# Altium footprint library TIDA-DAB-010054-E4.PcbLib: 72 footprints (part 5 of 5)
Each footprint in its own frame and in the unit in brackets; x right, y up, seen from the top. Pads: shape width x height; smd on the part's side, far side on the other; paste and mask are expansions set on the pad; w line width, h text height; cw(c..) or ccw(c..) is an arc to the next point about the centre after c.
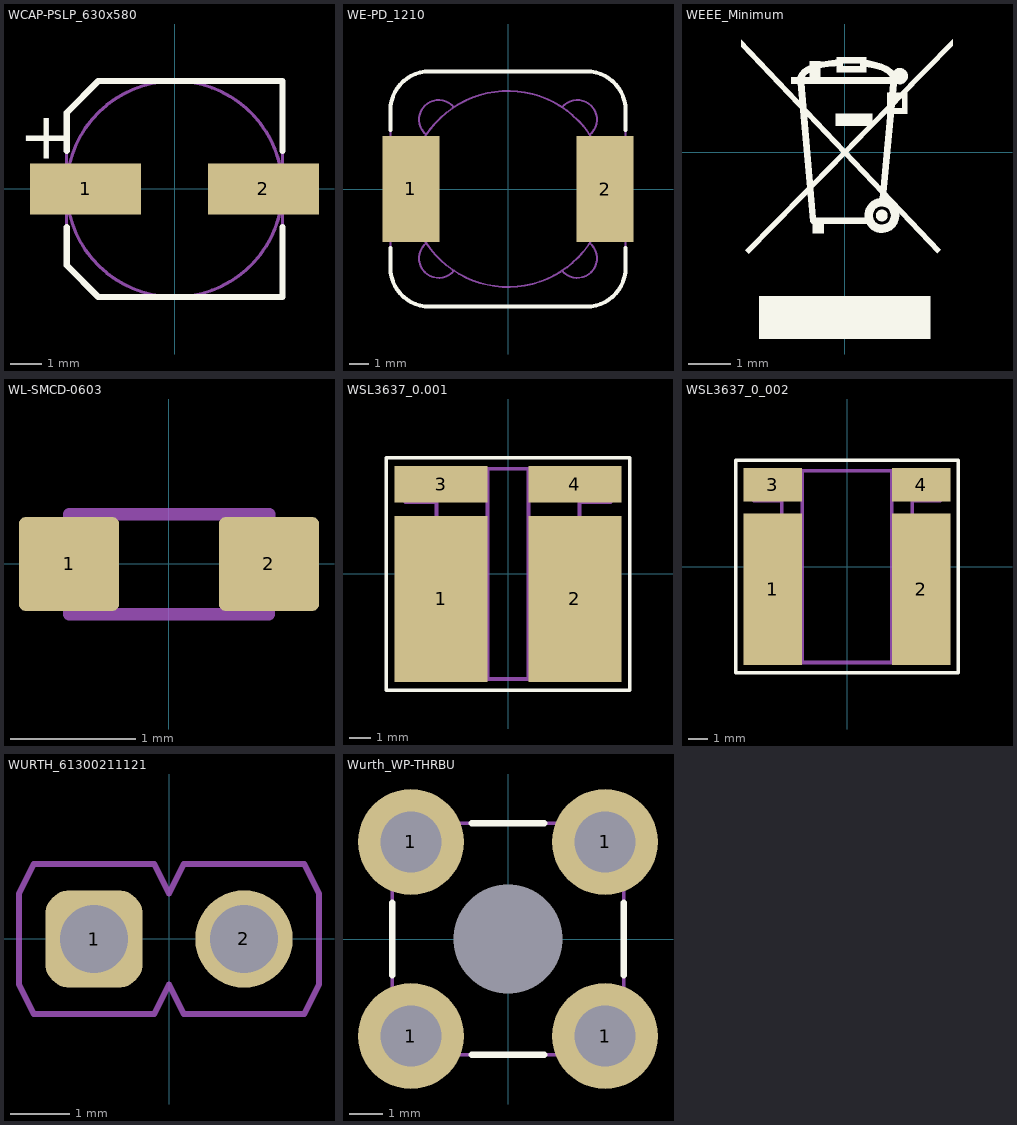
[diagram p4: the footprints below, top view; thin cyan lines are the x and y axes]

## WCAP-PSLP_630x580 [mm] "SMD, 2-Leads, Dia 6.3mm"
height 5.8
pads (2):
  rect 3.5x1.6 smd: 1(-2.8,0) 2(2.8,0)
Top Overlay:
  lines w0.2: -3.4,-1.2 -3.4,-2.4 -2.4,-3.4 3.4,-3.4 3.4,-1.2 ; -3.4,1.2 -3.4,2.4 -2.4,3.4 3.4,3.4 3.4,1.2
  text "+" at -4.9,0.95 h1.5
Mechanical 5:
  circle w0.1: c0,0 r3.4
  lines w0.1: -3.4,-2.4 -3.4,2.4 -2.4,3.4 3.4,3.4 3.4,-3.4 -2.4,-3.4 -3.4,-2.4
  text "+" at -4.072,-0.229 h0.51
  text ".Designator" at 0.703,0.254 h0.51
3D body: height 1, standoff 0, extent -3.4,-3.4 3.4,3.4
3D body: height 5.81, standoff 5.8, extent 2.404,-2.405 3.401,2.405
3D body: height 5.8, standoff 0.5, extent -3.399,-3.399 3.399,3.399

## WE-PD_1210 [mm] "Wurth Elektronik recommended land pattern"
height 10
pads (2):
  rect 2.9x5.4 smd: 1(-4.95,0) 2(4.95,0)
Top Overlay:
  lines w0.2: -6,-3 -6,-4.003 ccw(c-4,-4.003) -4,-6.003 4,-6.003 ccw(c4,-4.003) 6,-4.003 6,-3 ; -6,3 -6,4.003 cw(c-4,4.003) -4,6.003 4,6.003 cw(c4,4.003) 6,4.003 6,3
Mechanical 5:
  circle w0.1: c0,0.003 r5
  lines w0.1: -4.168,-2.758 ccw(c-3.536,-3.533) -2.761,-4.165 ; -4.168,2.764 cw(c-3.536,3.538) -2.761,4.171 ; 2.761,-4.165 ccw(c3.536,-3.533) 4.168,-2.758 ; 2.761,4.171 cw(c3.536,3.538) 4.168,2.764 ; -6,-3.997 ccw(c-4,-3.997) -4,-5.997 4,-5.997 ccw(c4,-3.997) 6,-3.997 6,4.003 ccw(c4,4.003) 4,6.003 -4,6.003 ccw(c-4,4.003) -6,4.003 -6,-3.997
  text ".Designator" at -0.711,-0.076 h0.51
3D body "WE-PD_1210.stp": height 10.01, standoff 0.01, extent -6,-6 6,6

## WEEE_Minimum [mm] "WEEElie bin"
height 9.2
Top Overlay:
  drawing of 23 lines, arcs and shapes, not listed

## WL-SMCD-0603 [mm] "SMD, 2-Leads, Body 1.6x0.8mm"
height 0.5
pads (2):
  rrect13% 0.8x0.75 smd: 1(-0.8,0) 2(0.8,0)
Mechanical 5:
  circle w0.1: c-0.659,-0.275 r0.075
  lines w0.1: -0.8,-0.4 0.8,-0.4 0.8,-0.171 0.78,-0.171 cw(c0.815,0) 0.78,0.171 0.8,0.171 0.8,0.4 -0.8,0.4 -0.8,0.171 -0.78,0.171 cw(c-0.815,0) -0.78,-0.171 -0.8,-0.171 -0.8,-0.4
  text ".Designator" at -0.395,0.657 h0.51
3D body "WL-SMCD-0603.stp": height 0.4, standoff 0, extent -0.8,-0.4 0.8,0.4

## WSL3637_0.001 [mil] "Vishay WSL3637 recommended land pattern for 0.001 to 0.0019 Ohm"
height 35
pads (4):
  rect 168x300 smd: 1(-121,-45) 2(121,-45)
  rect 168x66 smd: 3(-121,162) 4(121,162)
Top Overlay:
  lines w7: -220,-210 220,-210 220,-140 220,210 -220,210 -220,-210
Mechanical 5:
  lines w5: -185,-190 -185,0 -185,98 -129,98 -129,130 -185,130 -185,190 0,190 185,190 185,130 129,130 129,98 185,98 185,0 185,-190 0,-190 -185,-190
  text ".Designator" at 26.96,-14.15 h20
Mechanical 13:
  lines w7: -37,-190 -37,190 ; 37,-190 37,190 ; -185,-190 0,-190 185,-190 185,0 185,98 129,98 129,130 185,130 185,190 0,190 -185,190 -185,130 -129,130 -129,98 -185,98 -185,0 -185,-190
3D body: height 35, standoff 0, extent 37.02,-189.98 184.98,189.98
3D body: height 35, standoff 0, extent -36.98,-189.98 36.98,189.98
3D body: height 35, standoff 0, extent -184.98,-189.98 -37.02,189.98

## WSL3637_0_002 [mil] "Vishay WSL3637 recommended land pattern for 0.002 to 0.01 Ohm"
height 35
pads (4):
  rect 116x300 smd: 1(-147,-45) 2(147,-45)
  rect 116x66 smd: 3(-147,162) 4(147,162)
Top Overlay:
  lines w7: -220,-210 -220,210 220,210 220,-140 220,-210 -220,-210
Mechanical 5:
  lines w5: -185,-190 -185,0 -185,98 -129,98 -129,130 -185,130 -185,190 0,190 185,190 185,130 129,130 129,98 185,98 185,0 185,-190 0,-190 -185,-190
  text ".Designator" at 25.9,0.96 h20
Mechanical 13:
  lines w7: -89,-190 -89,190 ; 89,-190 89,190 ; -185,-190 0,-190 185,-190 185,0 185,98 129,98 129,130 185,130 185,190 0,190 -185,190 -185,130 -129,130 -129,98 -185,98 -185,0 -185,-190
3D body: height 35, standoff 0, extent 89.02,-189.98 184.98,189.98
3D body: height 35, standoff 0, extent -184.98,-189.98 -89.02,189.98
3D body: height 35, standoff 0, extent -88.98,-189.98 88.98,189.98

## WURTH_61300211121 [mm] "Header, 2.54mm, 2x1, TH"
height 8.89
pads (2):
  rrect50% 1.65x1.65 hole 1.15: 1(-1.27,0)
  round 1.65 hole 1.15: 2(1.27,0)
Mechanical 5:
  lines w0.1: -2.54,-0.77 -2.54,0.77 -2.29,1.27 -0.25,1.27 0,0.77 0.25,1.27 2.29,1.27 2.54,0.77 2.54,-0.77 2.29,-1.27 0.25,-1.27 0,-0.77 -0.25,-1.27 -2.29,-1.27 -2.54,-0.77
  text ".Designator" at 0.914,0.77 h0.51
3D body "61300211121.stp": height 8.54, standoff -3, extent -2.54,-1.27 2.54,1.27

## Wurth_WP-THRBU [mm] "Power Element Bush, M3, TH"
height 3
pads (9):
  round 3.2 hole 1.85: 1(-2.935,-2.935) 1(-2.935,2.935) 1(2.935,-2.935) 1(2.935,2.935)
  round 3.1 on Top Paste: ""(-2.935,-2.935) ""(-2.935,2.935) ""(2.935,-2.935) ""(2.935,2.935)
  round 3 hole 3.3 unplated mask+0.102: ""(0,0)
Top Overlay:
  lines w0.2: -3.5,-1.1 -3.5,1.1 ; -1.1,-3.5 1.1,-3.5 ; -1.1,3.5 1.1,3.5 ; 3.5,-1.1 3.5,1.1
Mechanical 5:
  lines w0.1: -3.5,-3.5 3.5,-3.5 3.5,3.5 -3.5,3.5 -3.5,-3.5
  text ".Designator" at -0.65,-0.249 h0.51
3D body "74650073R.stp": height 3, standoff -2.5, extent -3.5,-3.5 3.5,3.5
